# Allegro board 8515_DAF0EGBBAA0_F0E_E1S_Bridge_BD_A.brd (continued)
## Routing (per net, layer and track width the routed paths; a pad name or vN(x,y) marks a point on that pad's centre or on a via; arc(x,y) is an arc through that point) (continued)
FM_PRSNT_E1S_1_R_N: length 5.2
  TOP w0.109: U35.T14 131.82,31.43 131.58,31.2 v3(131.58,30.73) 131.58,30.25 R572.2 131.95,29.61 131.95,28.2 131.84,28.09 R556.1
FM_PRSNT_E1S_2_N: length 128.1
  TOP w0.109: v3(133.48,26.39) R557.2 ; v3(82.55,38) 83.03,38 83.14,37.9 J6.A12
  IN1 w0.124: v3(118.32,59.79) 118.54,59.79 119.28,60.53 120.68,60.53 121.48,61.33 123.41,61.33 124.19,60.55 128.22,60.55 128.71,61.05 131.27,61.05 131.87,60.45 132.66,60.45 133.33,61.13 135.43,61.13 136.21,60.34 136.21,54.17 136.08,54.04 136.08,52.7 136.21,52.57 136.21,49.61 136.13,49.54 136.13,46.32 135.94,46.13 135.94,44.1 136.6,43.45 136.6,39.75 137.19,39.15 138.66,39.15 139.15,38.67 142.37,38.67 143.13,37.91 143.13,36.79 143,36.67 143,31.92 141.63,30.55 141.63,29.07 142.16,28.54 142.16,26.27 140.41,24.52 138.93,24.52 138.15,25.3 136.47,25.3 135.92,25.85 134.01,25.85 v3(133.48,26.39)
  IN2 w0.124: v3(82.55,38) 83.31,37.24 86.49,37.24 92.33,43.08 93.75,43.08 95.66,41.17 100.45,41.17 100.72,40.9 107.51,40.9 107.98,40.43 v3(107.98,39.74)
  BOTTOM w0.109: v3(118.32,59.79) 118.32,59.76 118.16,59.6 118.16,56.16 117.74,55.13 116.99,54.39 116.51,54.07 116.22,53.95 114.22,51.94 114.22,50.19 111.59,47.57 110.59,47.57 108.78,45.76 108.78,41.04 v1(108.37,40.63) 108.23,40.49 108.23,40.21 107.98,39.96 v3(107.98,39.74)
FM_PRSNT_E1S_2_R_N: length 5.8
  TOP w0.109: R557.1 133.55,28.09 133.99,28.52 133.99,29.61 R573.2 133.88,30.53 133.88,31.09 133.03,31.95 v4(132.62,31.95) U35.T15
FM_PRSNT_E1S_3_N: length 56.2
  TOP w0.109: v3(106.76,37.31) 107.35,37.9 J7.A12 ; R694.2 v3(132.46,26.39)
  IN2 w0.124: v3(106.76,37.31) 106.76,36.86 106.89,36.74 108.35,36.74 110.04,38.42 110.04,39.27 110.4,39.63 111.06,39.63 111.33,39.36 114.18,39.36 115.79,40.97 115.79,43.75 116.35,44.31 118.18,44.31 118.8,43.69 119.69,43.69 120.1,43.29 120.1,41.6 119.6,41.11 119.09,41.11 118.85,40.87 118.85,36.12 119.05,35.92 120.6,35.92 120.95,35.57 120.95,34.6 121.44,34.11 122.76,34.11 122.95,33.92 122.95,33.88 122.98,33.85 122.98,33.55 122.95,33.52 122.95,33.08 122.98,33.05 122.98,32.75 122.95,32.72 122.95,30.32 123.62,29.65 125.52,29.65 126.01,30.14 132.24,30.14 132.86,30.77 v3(132.86,30.88)
  BOTTOM w0.109: v3(132.86,30.88) 132.86,29.54 v1(132.77,29.45) 132.77,29.05 132.92,28.89 132.92,28.3 132.46,27.84 v3(132.46,26.39)
FM_PRSNT_E1S_3_R_N: length 7.3
  TOP w0.109: R694.1 132.84,28.09 132.97,28.21 132.97,29.61 R697.2 132.72,30.37 133.02,30.37 133.32,30.67 133.32,31.15 133.1,31.37 132.57,31.37 132.21,31.73 132.21,32.91 U35.R14
FM_PWRDIS_E1S_0: length 121.2
  TOP w0.109: R542.2 v3(123.32,26.67) ; J4.B12 v3(29.34,37.89)
  IN2 w0.124: v3(29.34,37.89) 29.31,37.89 28.87,38.33 28.87,39.26 29.18,39.57 30.71,39.57 31.19,39.09 32.64,39.09 33.86,40.31 37.08,40.31 38.53,41.76 39.85,41.76 41.16,40.45 41.16,39.14 41.28,39.01 48.9,39.01 49.1,39.22 50.85,39.22 52.04,38.02 52.04,36.86 50.44,35.26 50.44,28.17 57.26,21.36 85.06,21.36 87.87,24.17 95.32,24.17 98.13,21.36 109.6,21.36 111.73,23.5 112.65,23.5 113.62,24.47 116.52,24.47 116.79,24.73 121.38,24.73 v3(123.32,26.67)
FM_PWRDIS_E1S_1: length 101.3
  TOP w0.109: J5.B12 52.12,37.9 v3(51.56,37.34) ; R544.2 v3(126.36,26.67)
  IN2 w0.124: v3(51.56,37.34) 51.56,37.02 49.97,35.43 49.97,28.11 57.1,20.98 82.28,20.98 88.85,14.41 95.28,14.41 101.85,20.99 109.76,20.99 110.12,21.34 112.4,21.34 113.11,22.05 113.11,23.32 113.74,23.95 116.71,23.95 117.29,23.37 120.58,23.37 122.38,25.17 124.87,25.17 v3(126.36,26.67)
FM_PWRDIS_E1S_2: length 91
  TOP w0.109: J6.B12 80.06,37.9 80.26,38.1 80.26,38.83 80.65,39.21 80.65,42.75 84.17,46.28 84.68,46.28 v3(86.16,47.75) ; v3(95.3,23.14) 94.24,23.14 93.61,23.77 89.08,23.77 88.8,24.05 88.8,25.86 87.66,27 87.66,27.95 87.03,28.58 87.03,29 v3(86.7,29.34) ; R545.2 v3(125.35,26.67)
  IN1 w0.124: v3(95.3,23.14) 100.56,23.14 104.32,19.39 108.81,19.39 110.21,17.99 113.08,17.99 113.28,17.78 114.94,17.78 116.72,19.57 116.72,19.98 118.71,21.97 121.79,21.97 122.54,22.72 122.54,23.24 125.35,26.05 v3(125.35,26.67)
  IN2 w0.124: v3(92.35,42.42) 88.96,39.02 88.96,37.22 88.49,36.75 87.71,36.75 86.79,35.84 86.79,30.76 86.41,30.38 86.41,29.68 86.7,29.4 v3(86.7,29.34)
  BOTTOM w0.109: v3(92.35,42.42) 92.35,45.77 91.44,46.69 86.49,46.69 86.16,47.02 v3(86.16,47.75)
FM_PWRDIS_E1S_3: length 28.6
  TOP w0.109: J7.B12 105.55,37.9 105.68,38.02 105.68,39.01 106.05,39.37 106.05,42.75 v3(107.44,44.14) 108.26,44.96 110.1,44.96 110.24,44.82 110.24,39.89 110.37,39.75 112.78,39.75 113.2,39.33 113.2,35.88 113.48,35.59 114.26,34.82 114.46,34.62 117.14,34.62 117.58,35.05 R700.2
FM_PWRDIS_E1S_R_0: length 6.9
  TOP w0.109: U35.T7 125.6,31.89 125.6,31.72 124.72,30.85 123.67,30.85 123.48,30.72 123.32,30.47 R565.2 123.83,29.61 123.83,28.2 123.72,28.09 R542.1
FM_PWRDIS_E1S_R_1: length 6.6
  TOP w0.109: U35.R8 127.38,32.93 127.38,31.98 126.94,31.54 126.94,30.47 126.59,30.12 R566.2 126.36,30.07 126.87,29.57 126.87,28.21 126.75,28.09 R544.1
FM_PWRDIS_E1S_R_2: length 5.7
  TOP w0.109: R545.1 125.62,28.09 125.86,28.32 125.86,29.61 R568.2 125.35,30.4 v3(126.49,31.54) 127.02,32.07 U35.T8
FM_PWRDIS_E1S_R_3: length 4.6
  TOP w0.109: R701.2 R700.1 119.27,35.29 120.52,36.55 120.52,37.19 120.63,37.3 U35.K1
HSC_SEL_ID0: length 10.4
  TOP w0.109: U35.F11 v4(129.82,40.9)
  BOTTOM w0.109: v4(129.82,40.9) 129.41,41.3 129.41,44.41 129.68,44.68 v1(129.68,45.37) 129.9,45.37 130.35,45.83 130.56,46.32 R519.1 131.06,47.48 131.06,48.58 130.56,49.09 R518.2
HSC_SEL_ID1: length 8.2
  TOP w0.109: R527.2 137.16,49.13 137.16,47.69 137.01,47.33 R528.1 136.65,46.52 v3(136.8,46.37) 136.16,46.37 133.49,43.7 U35.B16
HSC_SEL_ID2: length 14.5
  TOP w0.109: U35.C15 133.02,43.31 133.86,43.31 136.44,45.89 137.01,45.89 137.19,46.07 137.89,47.75 137.89,50.83 137.16,51.56 v3(136.73,51.56) 136.32,51.56 135.89,51.99 R533.1 R532.2
INA230_E1S_0_A0: length 4.8
  TOP w0.109: U11.2 12.83,50.8 12.32,51.31 12.32,51.58 R221.1 R219.1 9.63,52.22 9.4,52.45 v2(9.27,52.45)
INA230_E1S_0_A1: length 5.8
  TOP w0.109: U11.1 13.26,51.62 R223.1 R218.1 9.54,53.19 v2(8.76,53.98)
INA230_E1S_0_ALERT_R_N: length 3.9
  TOP w0.109: U11.3 12.05,50.3 R222.1 R217.1 9.63,50.06 v2(9.53,50.16)
INA230_E1S_1_A0: length 4.8
  TOP w0.109: U12.2 38.97,49.04 38.67,49.34 38.67,49.48 38.11,50.05 38.1,50.05 R237.1 ; R237.1 37.47,50.06 R234.1 ; R237.1 38.1,51.31 v2(37.72,51.69)
INA230_E1S_1_A1: length 6.3
  TOP w0.109: R233.1 v3(41.97,51.69) 41.27,51.69 41.21,51.63 v2(41.2,51.63) 40.53,52.3 39.6,52.3 39.22,51.92 R236.1 39.39,51.52 U12.1
INA230_E1S_1_ALERT_R_N: length 5
  TOP w0.109: R232.1 36.07,46.48 v2(36.07,47.62) 36.34,47.9 R238.1 38.25,47.9 38.86,48.51 38.86,48.54 U12.3
INA230_E1S_2_A0: length 4.6
  TOP w0.109: R249.1 62.19,33.17 R253.1 62.97,31.77 63.5,31.24 v2(63.5,31.11) 64.16,31.77 U13.2
INA230_E1S_2_A1: length 4.9
  TOP w0.109: v2(65.02,35.05) 64.62,34.65 R248.1 63.63,33.8 R252.1 64.39,33.66 65.05,33 U13.1
INA230_E1S_2_ALERT_R_N: length 5.1
  TOP w0.109: U13.3 64.52,31.27 64.52,31.24 64.39,31.11 64.39,30.25 R251.1 R247.1 61.72,30.88 v2(61.72,30.99)
INA230_E1S_3_A0: length 6.1
  TOP w0.109: U14.2 92.18,39.9 91.44,40.64 v2(91.44,42.16) 91.44,43.54 R267.1 R264.1
INA230_E1S_3_A1: length 5.5
  TOP w0.109: U14.1 92.73,41.93 93.47,42.67 v2(93.47,42.93) 93.47,43.18 93.07,43.58 R266.1 R263.1
INA230_E1S_3_ALERT_R_N: length 4.8
  TOP w0.109: R262.1 R268.1 90.93,38.25 v2(90.93,39.5) 91.06,39.5 91.16,39.4 U14.3
IO_EXP_INT: length 9.7
  TOP w0.109: U48.1 138.44,27.61 139.08,26.97 v3(139.92,26.97)
  BOTTOM w0.109: v3(139.92,26.97) 140.14,26.75 140.14,25.37 140.37,25.14 140.77,25.14 141,25.38 U44.7 141,26.88 141.45,27.33 141.73,27.33 142.29,27.89 R4604.1
IO_EXP_IO3: length 2
  TOP w0.109: v3(137.74,24.05) 137.4,23.71 U48.7
  BOTTOM w0.109: R4659.2 138.13,24.36 137.83,24.05 v3(137.74,24.05)
IO_EXP_IO4: length 1.9
  TOP w0.109: U48.8 137.41,23.06 v3(137.72,23.37)
  BOTTOM w0.109: v3(137.72,23.37) 137.79,23.44 R4660.2
IO_EXP_IO5: length 1.8
  TOP w0.109: U48.9 v3(137.69,22.41)
  BOTTOM w0.109: R4600.2 138.19,22.41 v3(137.69,22.41)
IO_EXP_IO6: length 1.8
  TOP w0.109: v3(137.72,21.71) 136.63,21.71 U48.10
  BOTTOM w0.109: v3(137.72,21.71) 138.22,21.71 R4601.2
IO_EXP_IO7: length 1.9
  TOP w0.109: U48.11 137.63,21.11 137.7,21.03 v3(137.7,21.05)
  BOTTOM w0.109: v3(137.7,21.05) 137.7,21.03 137.98,21.03 R4661.2
IO_EXP_IO8: length 2.7
  TOP w0.109: v3(143.74,19.81) 143.74,19.82 143.1,20.46 U48.13
  BOTTOM w0.109: R4662.2 143.74,19.86 v3(143.74,19.81)
IO_EXP_IO9: length 2.5
  TOP w0.109: v3(143.88,20.95) 143.73,20.95 143.57,21.11 U48.14
  BOTTOM w0.109: v3(143.88,20.95) 144.64,20.95 R4663.2
IO_EXP_IO10: length 2.4
  TOP w0.109: U48.15 143.54,21.76 v3(143.59,21.71)
  BOTTOM w0.109: R4664.2 143.6,21.69 v3(143.59,21.71)
IO_EXP_IO11: length 2.5
  TOP w0.109: U48.16 v3(143.89,22.41)
  BOTTOM w0.109: R4665.2 144.4,22.61 144.2,22.41 v3(143.89,22.41)
IO_EXP_IO12: length 2.6
  TOP w0.109: U48.17 v3(143.89,23.06)
  BOTTOM w0.109: v3(143.89,23.06) 144.14,23.06 144.6,23.52 R4666.2
IO_EXP_IO13: length 2.7
  TOP w0.109: U48.18 v3(143.89,23.71)
  BOTTOM w0.109: v3(143.89,23.71) 144.03,23.71 144.79,24.46 R4667.2
IO_EXP_IO14: length 3.3
  TOP w0.109: U48.19 v3(143.89,24.36)
  BOTTOM w0.109: v3(143.89,24.36) 143.96,24.36 144.81,25.2 R4668.2
IO_EXP_IO15: length 4.9
  TOP w0.109: U48.20 v3(143.84,25.01)
  BOTTOM w0.109: R4669.2 144.76,26.98 v1(144.8,26.94) 144.35,26.49 144.35,25.51 143.85,25.01 v3(143.84,25.01)
IO_EXP_RST: length 2.9
  BOTTOM w0.109: R4605.1 140.47,27.89 v1(140.35,27.77) 140.5,27.62 U44.6
IO_EXP_U44_IO4: length 7.3
  BOTTOM w0.109: R4597.1 136.24,19.91 v1(136.96,20.63) 136.96,20.1 137.32,19.74 139,19.74 140.46,20.34 141,20.89 U44.4
IRQ_INA230_E1S_0_ALERT_N: length 194.3
  TOP w0.109: v3(12.05,47.86) 12.05,49.02 R222.2 ; R620.1 v3(137.59,39.62)
  IN1 w0.124: v3(137.59,39.62) 137.59,40.18 137.85,40.44 137.85,50.83 138.53,52.47 138.53,55.61 138.08,56.07 138.08,58.3 138.69,58.91 v3(138.69,59.82)
  IN2 w0.124: v3(12.05,47.86) 15.18,47.86 16.18,46.86 20.57,46.86 22.91,44.53 29.41,44.53 30.94,46.05 31.93,46.05 33.34,47.46 36,47.46 38.53,49.99 42.16,49.99 43.23,48.92 43.23,47.57 43.95,46.85 45.86,46.85 49.39,43.32 55.36,43.32 57.58,45.54 58.53,45.54 63.78,50.8 63.78,52.48 64.72,53.42 64.72,58.67 65.94,59.9 70.29,59.9 71.08,59.11 71.08,57.2 70.8,56.92 70.6,56.92 70.32,56.65 70.32,56.21 70.6,55.94 72.1,55.94 72.98,55.06 72.98,46.05 74.88,44.15 81.49,44.15 83.14,45.8 98.17,45.8 99.94,44.02 106.48,44.02 107.64,45.18 108.3,45.18 110.24,47.12 110.48,47.12 111.46,48.11 112.75,48.64 114.78,50.68 114.78,51.04 114.78,51.89 118.49,55.6 118.49,56.67 118.77,56.95 122.81,56.95 123.26,57.39 123.26,59.32 123.95,60.02 125.85,60.02 125.93,60.1 127.69,60.1 128.78,61.19 131.26,61.19 132.63,59.82 v3(138.69,59.82)
IRQ_INA230_E1S_0_ALERT_R_N: length 4.9
  TOP w0.109: R620.2 135.74,39.74 135.23,40.26 v3(135.23,41.05) 135.23,41.36 134.89,41.71 133.02,41.71 U35.E15
IRQ_INA230_E1S_1_ALERT_N: length 152.3
  TOP w0.109: R238.2 37.39,46.89 v5(37.39,45.92)
  IN2 w0.124: v3(131.18,51.77) 131,51.6 131,50.68 132.07,49.6 132.07,46.4 131.85,46.17 131.85,38.89 132.62,38.11 132.62,32.62 133.55,31.69 133.55,30.56 132.71,29.72 126.29,29.72 125.85,29.28 125.85,28.49 125.46,28.1 113.42,28.1 113.3,27.99 112.77,27.99 110.98,26.19 110.98,25.61 109.35,23.98 97.61,23.98 95.43,26.16 90.39,26.16 90.06,26.49 87.99,26.49 84.19,22.7 69.68,22.7 68.08,24.3 68.08,25.73 68.04,25.77 67.65,25.77 67.08,26.34 66.94,26.34 65.93,27.34 65.64,27.34 65.37,27.62 65.37,27.82 64.83,28.35 64.04,28.35 63.63,28.76 62.81,28.76 62.4,28.35 61.8,28.35 61.1,29.05 61.1,30.01 60.35,30.76 58.34,30.76 57.93,31.17 57.93,31.92 57.49,32.36 55.14,32.36 54.07,33.43 54.07,39.63 52.9,40.79 49.99,40.79 48.63,42.15 43.32,42.15 40.56,44.91 38.4,44.91 v5(37.39,45.92)
  BOTTOM w0.109: R621.1 136.65,50.63 137.32,51.3 137.32,51.94 136.16,53.1 136.16,53.37 135.52,54.02 135.09,54.02 134.63,53.57 133.3,53.57 132.51,52.79 132.51,51.89 132.14,51.52 131.43,51.52 v3(131.18,51.77)
IRQ_INA230_E1S_1_ALERT_R_N: length 13.7
  TOP w0.109: U35.E14 v4(132.22,41.7)
  BOTTOM w0.109: R621.2 137.29,49.64 137.4,49.53 137.4,44.63 136.76,43.99 v1(136.76,42.2) 136.26,41.7 v4(132.22,41.7)
IRQ_INA230_E1S_2_ALERT_N: length 111.9
  TOP w0.109: R251.2 64.03,28.78 64.03,27.97 64.14,27.86 v3(64.65,27.86)
  IN2 w0.124: v3(134.23,49.08) 133.36,49.08 133.11,48.82 133.11,45.6 132.6,45.09 132.6,38.92 133.42,38.1 133.42,32.45 134.03,31.83 134.03,30.43 132.85,29.25 127.15,29.25 126.91,29 126.91,28.33 126.23,27.66 113.58,27.66 113.48,27.56 112.95,27.56 111.4,26.01 111.4,25.27 109.68,23.55 97.24,23.55 95.76,25.03 87.23,25.03 84.46,22.26 61.62,22.26 59.46,24.41 59.46,25.76 61.17,27.47 63.03,27.47 63.23,27.67 64.46,27.67 v3(64.65,27.86)
  BOTTOM w0.109: v3(134.23,49.08) 134.62,48.69 R622.1
IRQ_INA230_E1S_2_ALERT_R_N: length 8.4
  TOP w0.109: U35.E13 v4(131.42,41.7)
  BOTTOM w0.109: R622.2 134.62,44.16 v1(134.6,44.14) 134.6,43.42 134.49,43.31 132.8,43.31 132.42,42.92 131.98,42.92 131.83,42.77 131.83,42.27 131.42,41.85 v4(131.42,41.7)
IRQ_INA230_E1S_3_ALERT_N: length 98.2
  TOP w0.109: R268.2 92.02,36.94 92.05,36.91 v3(92.1,36.91) ; v3(135.25,60.31) 135.25,60.84 135.47,61.05 139.36,61.05 140.38,60.03 140.38,54.25 138.68,52.54 138.68,47.6 137.58,44.97 137.58,42.65 138.83,39.64 R726.1
  IN1 w0.124: v3(117.08,44.79) 119.25,46.96 119.25,54.65 119.71,55.76 119.98,56.03 120.44,56.22 123.37,56.22 123.5,56.1 123.5,55.09 123.87,54.72 127.14,54.72 127.94,53.92 128.76,53.92 130.78,55.94 132.01,55.94 133.22,56.44 135.25,58.47 v3(135.25,60.31)
  IN2 w0.124: v3(92.1,36.91) 92.1,35.44 92.44,35.11 95.96,35.11 96.45,35.6 100.88,35.6 101.74,36.46 101.74,37.27 102.51,38.04 104.12,38.04 106.49,40.41 107.24,40.41 107.51,40.14 107.51,39.54 107.78,39.26 108.22,39.26 110.24,41.29 110.24,43.43 111.95,45.14 111.95,46.15 112.27,46.47 112.66,46.73 113.81,46.73 114,46.54 115.52,46.54 117.08,44.98 v3(117.08,44.79)
IRQ_INA230_E1S_3_ALERT_R_N: length 8.4
  TOP w0.109: U35.F15 133.01,40.89 134.17,40.89 134.59,40.47 134.59,39.75 135.22,38.23 135.36,38.09 137.82,38.09 v3(138.03,37.88) R726.2
IRQ_P3V3_E1S_0_FLT_N: length 133
  TOP w0.109: U35.P2 v4(121.82,33.7) ; U26.C7 14.5,42.36 v3(14.86,42.72) ; v3(16.62,44.78) R191.1 16.27,44.41 16.15,44.7 16.15,44.81 15.79,45.17 U7.6
  IN2 w0.124: v3(14.86,42.72) 14.58,43 14.58,44.04 15.32,44.78 v3(16.62,44.78) 16.62,44.34 17.14,43.81 22.55,43.81 22.68,43.94 29.43,43.94 31.12,45.62 32.11,45.62 33.51,47.03 38.87,47.03 39.52,46.38 45.73,46.38 49.21,42.9 52.62,42.9 55.36,40.16 55.36,39.22 61.04,33.54 61.04,33.37 61.04,33.2 62,32.23 62,31.21 62.16,31.05 62.16,31.05 62.69,30.52 63.97,30.52 65.43,29.05 66.8,29.05 69.43,26.42 75.5,26.42 78.29,23.62 83.9,23.62 87.63,27.35 90.41,27.35 90.7,27.06 94.96,27.06 95.89,27.99 100.39,27.99 101,27.38 104.8,27.38 105.84,28.42 108.81,28.42 109.44,27.79 111.21,27.79 112.26,28.84 112.87,28.84 113.95,29.93 117.27,29.93 117.37,30.03 120.85,30.03 121.12,30.29 121.12,32.34 121.48,32.7 121.48,33.36 v4(121.82,33.7)
IRQ_P3V3_E1S_1_FLT_N: length 103.6
  TOP w0.109: U27.C7 43.58,41.51 v3(43.54,41.55) ; v3(44.89,43.17) 44.82,43.11 U8.6 ; U35.P3 v4(122.62,33.7)
  IN2 w0.124: v3(44.89,43.17) 45.42,42.65 48.74,42.65 50.16,41.22 53.24,41.22 54.81,39.65 v3(54.81,35.97) 54.81,33.68 55.68,32.82 57.91,32.82 58.37,32.36 58.37,31.6 58.63,31.34 61.15,31.34 62.59,29.89 63.12,29.89 64.19,28.82 64.98,28.82 65.28,28.52 66.65,28.52 68.51,26.65 68.51,24.48 69.86,23.13 84.01,23.13 87.81,26.92 90.23,26.92 90.57,26.59 104.62,26.59 106.02,27.99 108.46,27.99 109.12,27.33 111.51,27.33 112.59,28.41 113.1,28.41 114.18,29.5 117.5,29.5 117.59,29.59 121.16,29.59 121.56,30 121.56,32.08 122.2,32.72 122.2,33.28 v4(122.62,33.7)
  BOTTOM w0.109: v3(43.54,41.55) 43.54,41.89 43.76,42.11 R193.1 44.27,42.14 44.37,42.24 44.37,42.66 v3(44.89,43.17)
IRQ_P3V3_E1S_2_FLT_N: length 74.9
  TOP w0.109: R202.1 67.9,26.19 v3(67.84,26.24) U10.6 ; v3(112.1,25.22) 112.1,26.27 114.24,28.41 114.24,30.74 115.51,32.01 115.8,32.01 116.04,31.77 116.04,31.68 116.16,31.57 117.08,31.57 117.31,31.34 117.61,31.14 117.67,31.11 118.59,31.11 120.11,31.75 121.02,32.65 v4(121.02,32.9) U35.R1 ; v3(66.32,23.8) 65.96,23.44 U28.C7
  IN1 w0.124: v3(67.84,26.24) 67.84,25.67 66.32,24.15 v3(66.32,23.8) 66.73,23.39 70.94,23.39 72.82,25.27 76.81,25.27 80.17,28.63 82.31,28.63 83.6,27.34 83.69,27.34 84.6,26.43 84.95,26.43 90.34,31.83 94.49,31.83 95.4,30.91 101.73,30.91 104.12,28.53 108.79,28.53 v3(112.1,25.22)
IRQ_P3V3_E1S_3_FLT_N: length 42.1
  TOP w0.109: U35.R2 121.77,32.86 121.77,32.39 121.64,32.07 120.76,31.18 119.6,30.7 118.08,29.69 117.35,28.95 v4(117.35,28.65) ; R200.1 95.46,32.66 v3(94.97,32.66) 94.95,32.64 U9.6 ; v3(93.32,29.95) 92.96,29.59 U29.C7
  IN1 w0.124: v3(94.97,32.66) 95.15,32.49 103.05,32.49 104.27,33.71 105.56,33.71 106.55,32.72 107.44,32.72 107.75,33.02 107.75,34 107.91,34.16 108.47,34.16 108.82,33.81 109.75,33.81 110.11,34.17 110.11,34.74 110.23,34.87 112.22,34.87 114.71,32.38 114.71,31.11 115.93,29.9 117.07,29.9 117.35,29.62 v4(117.35,28.65)
  IN2 w0.124: v3(94.97,32.66) 94.97,31.6 v3(93.32,29.95)
IRQ_P3V3_EDGE_FLT_N: length 31.6
  TOP w0.109: R309.2 122.1,21.63 122.24,21.49 122.24,20.52 v3(121.81,20.08) ; U35.P10 v4(129.01,33.7)
  BOTTOM w0.109: v4(129.01,33.7) 129.44,34.12 130,34.12 130.2,33.92 130.2,33.54 130.6,33.14 130.6,32.66 131.94,31.33 133.06,31.33 133.4,30.99 133.46,30.84 133.46,30.66 133.37,30.45 133.37,29.59 133.94,29.03 133.94,28.51 132.97,27.54 132.97,26.21 132.19,25.43 132.19,23.31 131.93,23.04 131.93,20.98 130.44,19.49 129.75,19.49 129.37,19.11 126.36,19.11 125.94,19.53 122.02,19.53 121.81,19.75 v3(121.81,20.08)
IRQ_P12V_E1S_0_FLT_N: length 137.8
  TOP w0.109: U22.C7 19.97,57.45 v3(20.35,57.45) ; v3(23.24,56.39) 23.04,56.59 U3.6 ; U35.N4 v4(123.42,34.5)
  IN1 w0.124: v4(123.42,34.5) 123.26,34.5 122.89,34.87 122.43,34.87 122.22,35.08 122.22,35.59 122.1,35.71 119.99,35.71 119.84,35.56 116.15,35.56 115.97,35.75 114.34,35.75 113.27,36.82 111.81,36.82 111.31,37.32 110.59,37.32 109.31,38.6 109.31,38.96 109.31,39.21 108.26,40.26 105.67,40.26 103.3,42.62 97.14,42.62 96.45,43.31 94.99,43.31 92.35,45.95 85.84,45.95 84.19,44.29 83.83,44.29 83.41,44.29 82.93,44.77 82.52,44.77 81.19,43.44 79.1,43.44 77.67,42.01 74.7,42.01 72.77,40.08 72.77,38.05 70.46,35.74 67.26,35.74 62.94,40.06 60.96,40.06 58.3,42.72 56.9,42.72 55.98,43.64 48.62,43.64 45.9,46.35 41.04,46.35 40.16,47.24 32.64,47.24 30.1,44.7 23.88,44.7 22.27,46.31 22.27,53.11 22.36,53.2 22.36,55.51 v3(23.24,56.39)
  IN2 w0.124: v3(20.35,57.45) 22.17,57.45 v3(23.24,56.39)
  BOTTOM w0.109: R171.1 23.24,58.43 v3(23.24,56.39)
IRQ_P12V_E1S_1_FLT_N: length 114.8
  TOP w0.109: v3(45.03,56.59) 45.05,56.6 45.05,56.76 44.6,57.2 U23.C7 ; v3(90.3,39.01) 90.3,42.98 89.94,43.33 89.94,45.11 89.46,45.59 84.17,45.59 v3(83.79,45.21) ; v3(47.83,55.7) 47.83,55.88 47.81,55.9 U4.6 ; U35.P4 v4(123.42,33.7)
  IN1 w0.124: v3(105.99,35.69) 106.65,36.34 108.23,36.34 109.24,35.33 112.37,35.33 115.42,32.28 116.89,32.28 117.09,32.49 118.16,32.49 118.36,32.28 121.26,32.28 122.3,33.32 123.04,33.32 v4(123.42,33.7) ; v3(83.79,45.21) 83.22,45.78 82.31,45.78 80.83,44.3 74.3,44.3 72.34,46.25 72.34,48.51 70.61,50.24 67.49,50.24 63.04,45.8 57.18,45.8 55.96,44.58 48.9,44.58 47.75,45.72 47.75,55.45 47.83,55.52 v3(47.83,55.7) ; v3(96.94,33.31) 96.56,33.31 96.22,33.66 96.22,34.77 95.96,35.03 92.46,35.03 91.26,36.22 91.26,38.05 v3(90.3,39.01)
  IN2 w0.124: v3(45.03,56.59) 45.03,56.44 45.77,55.7 v3(47.83,55.7) ; v3(105.99,35.69) 105.85,35.55 105.47,35.55 104.37,34.44 101.22,34.44 99.39,32.61 97.64,32.61 v3(96.94,33.31)
  BOTTOM w0.109: R174.1 47.93,56.8 48.01,56.72 48.01,55.88 v3(47.83,55.7)
IRQ_P12V_E1S_2_FLT_N: length 78.3
  TOP w0.109: v3(70.83,56.42) 70.56,56.69 70.36,56.69 70.2,56.85 U24.C7 ; U5.6 73.33,54.18 v3(74.49,53.03) 74.41,52.95 R179.1 ; U35.P1 v4(121.04,33.72)
  IN1 w0.124: v3(110.64,39.14) 110.64,39.63 108.77,41.5 108.3,41.5 108.3,41.49 106.18,41.49 103.75,43.92 98.67,43.92 95.41,47.18 83.21,47.18 82.73,46.7 81.89,46.7 80.4,45.21 74.75,45.21 73.3,46.67 73.3,52.6 73.72,53.03 v3(74.49,53.03)
  IN2 w0.124: v3(70.83,56.42) 72.3,56.42 73.85,54.87 73.85,53.66 v3(74.49,53.03) ; v4(121.04,33.72) 120.06,34.7 118.75,34.7 118.5,34.94 117.58,34.94 117.03,34.39 113.87,34.39 112.57,35.69 109.56,35.69 109.43,35.81 109.43,36.63 110.64,37.84 v3(110.64,39.14)
IRQ_P12V_E1S_3_FLT_N: length 61.3
  TOP w0.109: R182.1 98.88,53.54 98.88,54.27 v3(99.15,54.54) 98.81,54.89 U6.6 ; U25.C7 95.68,57 96.17,56.52 v3(96.39,56.52) ; U35.P5 v4(124.22,33.7) ; v3(109.58,45.59) 109.65,45.61 110.45,45.28 113.17,45.28 113.83,45.01 114.32,44.68 115.39,43.61 115.39,42.13 114.93,41.02 113.58,39.67 113.58,36.04 113.76,35.87 114.42,35.2 114.83,35.2 114.84,35.2 v3(114.93,35.1)
  IN1 w0.124: v4(124.22,33.7) 123.96,33.7 123.55,34.11 122.28,34.11 121.89,34.49 119.86,34.49 119.35,35 117.75,35 117.2,34.44 115.59,34.44 v3(114.93,35.1) ; v3(99.15,54.54) 98.86,54.25 98.86,52.81 98.33,52.28 98.33,46.83 100.31,44.85 105.48,44.85 106.47,45.84 107.69,45.84 108.92,47.07 110.24,47.07 110.72,46.58 110.72,45.8 110.35,45.42 109.74,45.42 v3(109.58,45.59)
  IN2 w0.124: v3(96.39,56.52) 96.49,56.41 98.5,56.41 98.62,56.29 98.62,54.9 98.97,54.54 v3(99.15,54.54)
IRQ_P12V_EDGE_FLT_N: length 2.8
  TOP w0.109: U35.T11 v4(129.02,32.1)
  BOTTOM w0.109: R4589.2 128.9,30.63 128.9,31.99 v4(129.02,32.1)
IRQ_P12V_EDGE_FLT_N_R: length 169.2
  TOP w0.109: v3(7.67,29.47) 8.14,29.47 U33.C7 ; U34.9 18.48,33.96 18.59,34.07 18.59,34.62 v3(19.27,35.3)
  IN1 w0.124: v3(116.25,19.96) 114.51,18.21 113.46,18.21 113.25,18.42 110.39,18.42 108.99,19.82 104.49,19.82 99.94,24.37 96.61,24.37 96.38,24.6 89.61,24.6 85.7,20.7 74.85,20.7 71.76,17.6 62.06,17.6 61.45,18.21 60.65,18.21 59.72,19.14 53.46,19.14 53.44,19.13 53.44,19.13 48.84,14.53 42.6,14.53 38.17,18.95 v3(26.51,18.95)
  IN2 w0.124: v3(7.67,29.47) 8.15,29.47 8.33,29.65 8.33,31.18 8.86,31.71 8.86,35.14 8.66,35.35 8.66,36.15 8.93,36.42 8.98,36.42 10.27,37.72 11.76,37.72 15.7,36.09 18.95,36.09 19.27,35.76 v3(19.27,35.3) 19.9,35.3 23.5,31.7 23.5,19.94 24.48,18.95 v3(26.51,18.95)
  BOTTOM w0.109: v3(116.25,19.96) 117.36,19.96 117.45,20.05 117.54,20.05 120,22.51 120,22.72 121.01,23.74 124.48,23.74 125.1,23.12 125.1,22.24 125.42,21.92 129.56,21.92 129.86,22.22 129.86,22.51 129.7,22.88 129.7,25.41 129.96,25.67 129.96,26.72 129.89,26.78 129.89,28.87 129.6,29.16 129.57,29.16 R4589.1 129.69,29.59 129.9,29.59 R512.2
IRQ_P12V_HSC_ALERT1_N: length 8.2
  TOP w0.109: U35.R3 v4(122.62,32.9)
  BOTTOM w0.109: v4(122.62,32.9) 122.62,32.72 122.94,32.4 122.94,31.69 122.37,31.12 121.74,31.12 120.88,30.76 120.62,30.76 119.96,30.49 119.76,30.29 119.76,28.2 119.65,28.09 R707.2
IRQ_P12V_HSC_ALERT2_N: length 5.1
  TOP w0.109: v4(122.01,31.88) 122.14,32.02 122.14,32.41 122.22,32.48 U35.T2
  BOTTOM w0.109: R708.2 118.44,30.33 118.59,30.33 119.04,30.77 119.56,31.12 119.75,31.2 120.05,31.5 120.97,31.88 v4(122.01,31.88)
IRQ_SMB_ALERT_N: length 162.5
  TOP w0.109: v3(132.59,10.68) 132.59,10.29 130.02,7.72 115.63,7.72 115.05,8.3 113.44,8.97 108.18,8.97 106.37,10.77 v3(106.37,11.72)
  IN1 w0.124: v3(13.66,9.53) 13.77,9.64 14.41,9.64 14.53,9.52 21.05,9.52 24.68,13.15 24.68,16.72 25.1,17.13 27.4,17.13 27.9,17.64 34.61,17.64 40.25,12 55.36,12 56.18,11.18 97.65,11.18 98.44,11.96 106.14,11.96 106.37,11.73 v3(106.37,11.72) ; v3(132.59,10.68) 132.59,11.91 133.53,12.85 133.53,15.97 134.39,16.83 134.39,19.67 134,20.06 132.88,20.06 132.39,20.55 131.26,20.55 v3(129.39,22.42)
  BOTTOM w0.109: v3(129.39,22.42) 129.32,22.49 129.32,25.41 128.85,25.88 128.85,26.37 128.92,26.44 128.92,27.52 128.4,28.04 R185.2 128.8,28.09 128.91,28.2 128.91,29.08 128.67,29.32 R552.1 ; GF1.OCP_A11 v3(13.66,9.53)
IRQ_SMB_ALERT_R_N: length 6.2
  TOP w0.109: U35.P9 v4(128.22,33.7)
  BOTTOM w0.109: v4(128.22,33.7) 128.39,33.7 128.82,33.27 129.42,33.27 v1(129.69,33.01) 129.69,32.64 129.58,32.53 128.74,32.53 128.61,32.41 128.61,30.9 128.4,30.68 R552.2
IRQ_TMP75_ALERT_N: length 67.4
  TOP w0.109: U35.L4 v4(123.42,36.1)
  IN2 w0.124: v3(122.66,57.5) 120.84,57.5 119.79,58.55 117.78,58.55 117.5,58.27 117.5,56.01 113.85,52.35 113.85,50.96 112.26,49.37 111.48,49.05 104.62,49.05 103.84,48.26 103.84,45.9 103.25,45.31 100.57,45.31 97.14,48.74 v3(96.39,48.74) ; v3(127.05,56.49) 127.05,56.23 125.75,54.94 125.75,53.89 126.18,53.47 126.18,52.41 125.81,52.04 125.12,52.04 124.72,51.64 124.72,50.58 124.61,50.47 124.13,50.47 123.74,50.08 123.74,47.9 123.78,47.85 123.78,41.98 122.98,41.18 122.98,38.84 123.83,38 123.83,36.35 123.58,36.1 v4(123.42,36.1)
  BOTTOM w0.109: v3(122.66,57.5) 123.45,57.5 123.87,57.08 124.58,57.08 126.02,56.48 127.04,56.48 v3(127.05,56.49) ; R291.1 96.08,49.05 v3(96.39,48.74)
JTAG_BIC_DEBUG_R_TDO: length 3.5
  TOP w0.109: U35.A11 129.42,44.86 130.91,46.35 130.91,46.59 131.29,46.97 R674.2
JTAG_BIC_DEBUG_TCK: length 17.3
  TOP w0.109: R4585.2 v3(129.16,57.53) ; U35.D10 v4(129.01,42.5)
  BOTTOM w0.109: v3(129.16,57.53) 129.59,57.1 129.59,56.33 129.38,56.12 129.38,49.99 128.78,49.39 128.78,48.75 129.03,48.5 129.03,46.73 129.19,46.57 129.19,46.09 128.81,45.71 128.81,45.31 128.85,45.27 128.85,43.66 128.61,43.41 128.61,42.91 v4(129.01,42.5)
JTAG_BIC_DEBUG_TCK2: length 4.3
  TOP w0.109: U35.A13 131.02,44.73 131.23,44.95 131.23,44.96 v4(131.24,44.96)
  BOTTOM w0.109: R4615.2 133.6,46.09 v1(132.41,44.89) 131.3,44.89 v4(131.24,44.96)
JTAG_BIC_DEBUG_TCK_R: length 4.4
  TOP w0.109: 133.54,56.52 133.49,56.47 v3(131.86,56.47) 131.64,56.47 R4585.1 R4581.1
JTAG_BIC_DEBUG_TDI: length 18.7
  TOP w0.109: R4586.2 129.28,59.56 v3(129.13,59.41) ; U35.C10 v4(129.01,43.3)
  BOTTOM w0.109: v4(129.01,43.3) 129.15,43.43 129.15,45.4 129.25,45.65 129.52,45.92 129.88,45.92 130.11,46.15 130.16,46.27 130.16,46.49 130.04,46.62 130.04,48.74 129.74,49.46 129.74,55.88 129.97,56.11 129.97,58.76 129.31,59.41 v3(129.13,59.41)
JTAG_BIC_DEBUG_TDI2: length 5.7
  TOP w0.109: U35.D11 v4(129.82,42.5)
  IN1 w0.124: v4(129.82,42.5) 129.53,42.5 129.41,42.62 129.41,45.6 v3(128.74,46.27)
  BOTTOM w0.109: R4616.2 128.52,46.49 v3(128.74,46.27)
JTAG_BIC_DEBUG_TDI_R: length 4.4
  TOP w0.109: R4582.1 R4586.1 130.58,59.49 v3(131.21,58.86) 131.4,59.05 J2.8
JTAG_BIC_DEBUG_TDO: length 15.6
  TOP w0.109: J2.6 132.33,57.78 131.72,58.39 130.9,58.39 130.75,58.55 R4583.1 130.58,58.11 130.62,58.06 130.75,58.06 v3(131.22,57.59) ; R674.1 131.57,48.81 v3(131.35,49.02)
  BOTTOM w0.109: v3(131.22,57.59) 130.36,56.73 130.36,55.93 130.08,55.65 130.08,52.17 130.96,51.29 131.05,51.08 131.05,49.17 131.2,49.02 v3(131.35,49.02)
JTAG_BIC_DEBUG_TDO2: length 4.7
  TOP w0.109: U35.C11 v4(129.82,43.3)
  IN1 w0.124: v4(129.82,43.3) 129.82,43.35 130.19,43.72 130.19,45.78 129.68,46.28 v3(129.68,46.35)
  BOTTOM w0.109: v3(129.68,46.35) 129.68,46.83 R4617.2
JTAG_BIC_DEBUG_TMS: length 14.4
  TOP w0.109: v3(132.05,52.13) 132.05,52.12 131.95,52.01 131.95,50.71 131.37,50.13 131.37,49.68 132.08,48.98 132.08,46.38 131.45,45.75 130.79,45.75 129.82,44.77 v4(129.82,44.1) U35.B11 ; v3(131.12,54.02) 130,54.02 129.77,54.25 R4584.2
  BOTTOM w0.109: v3(132.05,52.13) 132.05,53.09 v3(131.12,54.02)
JTAG_BIC_DEBUG_TMS2: length 7.1
  TOP w0.109: U35.B12 v4(130.62,44.1)
  IN1 w0.124: v3(131.4,46.36) 131.36,46.32 130.74,46.32 130.62,46.19 v4(130.62,44.1)
  BOTTOM w0.109: v3(131.4,46.36) 131.54,46.5 v4(131.54,48.14) 131.54,48.56 131.92,48.94 131.92,49.29 R4618.2
JTAG_BIC_DEBUG_TMS_R: length 4.3
  TOP w0.109: R4584.1 R4580.1 130.94,55.5 v3(131.16,55.28) 131.38,55.5 132.11,55.5 132.36,55.24 J2.2
JTAG_BIC_NTRST1: length 7.2
  TOP w0.109: R675.2 132.46,49.17 133.1,48.53 133.1,47.24 132.82,46.97 R596.2 132.59,46.25 v4(132.27,45.94) 131.75,45.42 130.93,45.42 130.22,44.7 U35.A12
JTAG_BIC_NTRST2: length 10.4
  TOP w0.109: U35.B13 v4(131.42,43.3)
  BOTTOM w0.109: R4613.2 R4614.2 133.6,49.05 134.1,48.55 134.1,45.47 134.29,45.29 134.29,44.53 133.55,43.79 v1(133.29,43.79) 132.01,43.79 131.52,43.3 v4(131.42,43.3)
JTAG_BIC_SRST_N: length 3.7
  TOP w0.109: J2.10 132.56,60.33 132.16,60.73 v3(132.16,61.06) 131.62,61.59 R4587.1
LED_BIC_E1S_0: length 122
  TOP w0.109: v3(39.69,39.87) 37.28,39.87 37.21,39.8 35.64,39.8 35.19,39.36 R216.1 34.66,39.17 34.59,39.09 J4.A10 ; R551.2 v3(128.4,28.7)
  IN2 w0.124: v3(128.4,28.7) 128.24,28.7 126.96,27.42 126.96,26.53 125.06,24.63 122.4,24.63 120.11,22.34 118.52,22.34 117.97,22.89 115.37,22.89 114.96,22.48 114.96,21.01 113.47,19.52 112.06,19.52 111.5,20.08 102.16,20.08 95.63,13.55 87.68,13.55 87.08,14.15 62.19,14.15 49.11,27.23 49.11,36.2 47.21,38.1 40.43,38.1 39.69,38.84 v3(39.69,39.87)
LED_BIC_E1S_1: length 119.8
  TOP w0.109: R553.2 128.8,27.29 128.91,27.18 128.91,25.85 129.33,25.43 130.79,25.43 131.29,24.92 131.29,23.48 130.8,22.99 v3(130.16,22.99) ; v3(115.66,31.41) 114.65,30.39 114.65,26.54 112.83,24.72 112.83,21.21 113.12,20.92 114.69,20.92 v3(115.13,20.48) ; v3(62.51,34.47) 62.36,34.62 62.36,35.17 63.43,36.24 63.87,36.24 64.22,36.59 64.22,37.08 63.12,38.18 v2(63.12,39.42) 62.72,39.83 61.35,39.83 60.81,39.29 R231.1 60.74,39.17 60.67,39.1 J5.A10
  IN2 w0.124: v3(62.51,34.47) 62.87,34.47 64.25,33.09 64.25,31.99 65.94,30.29 67.35,30.29 67.67,30.6 69.14,30.6 69.37,30.37 69.37,28.75 70.44,27.68 79.5,27.68 80.26,28.45 83.19,28.45 83.81,27.83 85.53,27.83 86.94,28.41 88.04,29.51 91.67,29.51 91.81,29.37 93.53,29.37 95.61,31.45 95.61,33.12 96.72,34.24 98.58,34.24 99.29,34.95 103.91,34.95 104.6,35.64 104.83,35.64 105.52,36.33 108.14,36.33 109.83,34.65 109.83,31.75 110.17,31.41 v3(115.66,31.41)
  BOTTOM w0.109: v3(130.16,22.99) 130.16,22.77 130.24,22.58 130.24,22.06 129.69,21.51 124.31,21.51 122.47,23.35 121.38,23.35 119.9,21.88 119.9,20.83 119.4,20.32 118.36,20.32 117.37,19.33 116.03,19.33 115.13,20.23 v3(115.13,20.48)
LED_BIC_E1S_2: length 73.8
  TOP w0.109: R246.1 88.32,38.63 v2(87.83,39.12) 86.36,39.12 v3(86.11,38.86) 86.11,38.7 85.76,38.35 85.22,38.35 84.48,39.1 J6.A10 ; R554.2 v3(129.41,28.7)
  IN1 w0.124: v4(121.02,36.9) 121.42,36.5 126.07,36.5 126.19,36.38 126.19,33.91 127.58,32.51 128.07,32.51 128.52,32.07 128.52,31.26 129.41,30.37 v3(129.41,28.7)
  IN2 w0.124: v3(86.11,38.86) 87.5,38.86 92.13,43.48 93.98,43.48 95.91,41.56 100.82,41.56 100.98,41.4 109.35,41.4 109.81,41.86 109.81,43.74 111.52,45.45 111.52,46.35 112.19,47.02 113.02,47.36 113.78,47.36 114.15,47 117.82,47 118.3,46.52 118.69,46.52 120.41,46.52 122.22,44.7 122.22,38.11 v4(121.02,36.9)
LED_BIC_E1S_3: length 37.6
  TOP w0.109: v3(112.22,37.31) 111.8,37.74 R261.1 111.41,37.49 110.77,37.49 110.5,37.75 110.5,38.41 109.81,39.1 J7.A10 ; R725.2 v3(129.41,26.19)
  IN1 w0.124: v3(129.41,26.19) 129.42,26.19 130.95,27.73 130.95,30 130.28,30.68 130.28,32.31 129.26,33.32 127.62,33.32 126.98,33.96 126.98,38.07 126.65,38.41 123.41,38.41 122.93,38.89 117.41,38.89 117.02,39.28 116.36,39.28 115.77,39.88 114.75,39.88 113.7,38.83 112.73,38.83 112.22,38.33 v3(112.22,37.31)
LED_BIC_E1S_R_0: length 3.9
  TOP w0.109: R551.1 128.4,30.94 129.79,32.33 129.79,32.92 U35.R11
LED_BIC_E1S_R_1: length 5.4
  TOP w0.109: U35.T12 130.22,32.23 129.53,31.55 v3(129.53,31.25) 128.91,30.63 128.91,28.21 128.78,28.09 R553.1
LED_BIC_E1S_R_2: length 3.8
  TOP w0.109: U35.R12 130.61,32.91 130.61,32.21 130.07,31.68 130.07,31.16 129.41,30.49 R554.1
LED_BIC_E1S_R_3: length 5.4
  TOP w0.109: U35.T13 131.02,31.97 v3(130.76,31.71) 130.76,31.39 129.93,30.56 129.93,28.15 129.84,28.06 129.44,28.06 R725.1
LED_P12V_AUX: length 3.5
  TOP w0.109: v3(144.21,19.17) 144.75,18.63 v2(145.21,18.63) 145.21,19.27 144.91,19.57 D10.1
  BOTTOM w0.109: v3(144.21,19.17) 144.21,19.17 144.21,19.19 144.32,19.09 144.67,19.09 R296.2
LED_P12V_E1S_ALL_GOOD: length 10.4
  TOP w0.109: v3(145.68,26.41) 145.69,26.4 145.69,25.88 145.58,25.77 D11.C
  IN1 w0.124: v3(145.68,26.41) 144.95,26.41 144.83,26.54 144.83,29.03 144.42,29.44 144.42,31.63 144.71,31.92 v3(145.08,31.92)
  BOTTOM w0.109: v1(145.62,31.18) 145.62,31.38 v3(145.08,31.92) U17.D
LED_P12V_E1S_ALL_GOOD_R: length 11
  TOP w0.109: v3(145.66,27.05) 145.42,26.81 144.44,26.81 144.32,26.68 144.32,24.6 144.65,24.27 D11.A
  IN1 w0.124: v3(145.66,27.05) 145.66,30.33 145.53,30.45 v3(145.11,30.45)
  BOTTOM w0.109: R297.2 143.89,30 143.89,30.34 144.01,30.45 v1(144.38,30.45) v3(145.11,30.45)
LED_PWRGD_P12V_E1S_ALL: length 41.2
  TOP w0.109: U35.N5 v4(124.22,34.5)
  IN1 w0.124: v4(124.22,34.5) 124.4,34.5 124.79,34.11 125.25,34.11 125.43,33.93 125.43,32.57 125.76,32.24 126.51,32.24 126.94,31.81 126.94,30.83 127.15,30.62 127.79,30.62 128.94,29.47 128.94,25.77 129.29,25.42 131.69,25.42 131.92,25.64 131.92,26.56 132.74,27.38 133.76,27.38 134.24,26.9 136.47,26.9 137.26,26.11 138.65,26.11 v3(139.23,25.53) 140.28,25.53 141.35,26.6 141.35,28.2 140.82,28.73 140.82,30.35 140.01,31.17 140.01,32.68 v3(141.54,34.21)
  BOTTOM w0.109: v3(141.54,34.21) 140.91,34.21 140.8,34.32 140.8,35.88 140.92,36 v1(141.16,36) 141.4,36 141.54,35.87 R4670.1 ; R298.1 139.26,25.56 v3(139.23,25.53)
LED_PWRGD_P12V_E1S_ALL_R: length 4.3
  BOTTOM w0.109: U17.G C304.1 143.34,35.61 142.96,35.99 v1(142.52,35.99) 142.5,35.99 142.34,35.83 R4670.2
Net_78: length 0.6
  TOP w0.109: 131.82,42.9 v4(132.22,43.3)
Net_98: length 0.6
  TOP w0.109: 131.02,38.1 v4(131.42,37.7)
Net_99: length 0.6
  TOP w0.109: 132.62,37.3 v4(133.01,36.9)
Net_100: length 0.6
  TOP w0.109: 131.82,37.3 v4(132.22,36.9)
Net_101: length 0.6
  TOP w0.109: 130.22,42.9 v4(130.62,43.3)
Net_103: length 0.6
  TOP w0.109: 132.62,38.9 v4(133.01,39.3)
Net_104: length 0.6
  TOP w0.109: 129.42,41.3 v4(129.82,41.7)
Net_107: length 0.6
  TOP w0.109: 133.42,39.7 v4(133.82,40.1)
Net_110: length 0.6
  TOP w0.109: 132.62,39.7 v4(133.01,40.1)
Net_113: length 0.6
  TOP w0.109: 128.62,33.3 v4(129.01,32.9)
Net_117: length 0.6
  TOP w0.109: 130.22,35.7 v4(130.62,35.3)
Net_118: length 0.6
  TOP w0.109: 129.42,34.9 v4(129.82,34.5)
Net_119: length 0.6
  TOP w0.109: 131.82,38.1 v4(132.22,37.7)
Net_121: length 0.6
  TOP w0.109: 122.22,35.7 v4(121.82,35.3)
Net_122: length 0.6
  TOP w0.109: 130.22,34.9 v4(130.62,34.5)
Net_809: length 0.6
  TOP w0.109: 124.62,42.9 v4(124.22,43.3)
Net_811: length 0.6
  TOP w0.109: 123.82,42.9 v4(123.42,43.3)
OSC1_OE: length 4
  TOP w0.109: R319.1 121.16,53.01 v3(121.22,53.07) 121.24,53.09 121.54,53.09 121.67,53.21 121.67,55.15 121.78,55.26 OSC1.1
OSC1_VDD:
  vias: v3(123.7,53.72)
OSC1_VDD_R:
  vias: v3(124.07,55.74)
P3E_E1S_0_RX_DN0: length 43.7
  TOP w0.132: v3(30.54,35.1) 30.87,34.76 31.89,34.76 32.02,34.89 J4.A17
  BOTTOM w0.132: GF1.A17 29.45,3.16 29.58,3.29 29.58,5.19 29.78,5.6 30.29,6.64 32.69,10.07 32.83,10.86 v4(32.83,11.69) 32.83,14.23 25.23,23.46 25.23,23.47 25.06,23.67 24.03,29.03 24.02,29.61 24.24,30.16 25.83,34.07 26.87,34.79 27.47,34.79 27.47,34.8 30.23,34.8 v3(30.54,35.1)
P3E_E1S_0_RX_DN1: length 43.6
  TOP w0.132: J4.A20 33.6,33.09 33.73,32.96 34.33,32.96 v3(34.67,33.3)
  BOTTOM w0.132: GF1.A20 31.25,3.16 31.38,3.29 31.38,4.72 31.74,5.6 31.79,5.74 32.56,7.66 33.18,8.55 33.88,9.53 34.28,11.83 34.28,14.4 v4(29.81,19.83) 26.44,23.94 25.9,28.61 25.9,29.23 26.15,30.65 26.64,31.14 27.23,31.14 27.28,31.15 27.54,31.23 27.61,31.27 29.15,32.36 29.85,32.6 30.75,32.6 31.49,32.99 32.44,32.99 32.86,32.81 33.22,32.81 33.68,32.95 33.95,32.99 34.36,32.99 v3(34.67,33.3)
P3E_E1S_0_RX_DN2: length 36.7
  TOP w0.132: J4.A23 32.02,31.29 31.86,31.14 31.37,31.14 30.67,30.44 30.36,30.44 v3(30.03,30.78)
  BOTTOM w0.132: v3(30.03,30.78) 29.69,30.44 28.97,30.44 28.3,29.77 27.96,29.29 27.79,28.29 27.79,24.39 34.95,15.67 v4(35.08,15.51) 35.43,15.09 35.81,14.63 35.41,9.39 33.71,6.96 33.4,5.6 33.18,4.66 33.18,3.29 33.05,3.16 GF1.A23
P3E_E1S_0_RX_DN3: length 35.8
  TOP w0.132: v3(34.62,29.7) 34.28,29.36 33.73,29.36 33.6,29.49 J4.A26
  BOTTOM w0.132: v3(34.62,29.7) 34.28,29.36 33.4,29.36 32.77,28.72 32.77,27.77 33.16,27.2 35.25,24.24 35.4,24.03 35.45,23.96 35.65,23.65 35.83,23.39 35.85,23.29 v4(35.9,22.94) 35.96,22.54 36.14,21.27 36.52,20.99 37.11,21.08 37.26,20.97 37.33,20.47 37.22,20.32 36.63,20.23 36.35,19.86 36.46,19.08 36.83,18.8 37.43,18.89 37.57,18.77 37.65,18.28 37.54,18.13 36.94,18.04 36.66,17.66 37.18,14.08 37.01,12.07 36.99,11.95 36.69,8.49 35.46,7.26 34.98,6.19 34.98,3.29 34.85,3.16 GF1.A26
P3E_E1S_0_RX_DP0: length 43.7
  TOP w0.132: v3(30.54,34.09) 30.87,34.42 31.89,34.42 32.02,34.29 J4.A18
  BOTTOM w0.132: v3(30.54,34.09) 30.16,34.46 27.61,34.46 27.61,34.45 26.98,34.45 26.11,33.85 25.96,33.48 26.07,33.21 25.93,32.85 25.66,32.74 25.51,32.37 25.62,32.1 25.47,31.74 25.21,31.62 25.06,31.26 25.17,30.99 25.02,30.63 24.75,30.51 24.36,29.55 24.37,29.06 24.37,29.06 25.37,23.82 25.49,23.68 v4(27.38,21.38) 33.17,14.35 33.17,10.83 33.01,9.94 30.58,6.47 30.16,5.6 29.92,5.11 29.92,3.29 30.05,3.16 GF1.A18
P3E_E1S_0_RX_DP1: length 43.6
  TOP w0.132: J4.A21 33.6,32.49 33.73,32.62 34.33,32.62 v3(34.67,32.29)
  BOTTOM w0.132: GF1.A21 31.85,3.16 31.72,3.29 31.72,4.66 32.1,5.6 32.11,5.61 32.87,7.5 33.46,8.35 33.46,8.35 34.2,9.4 34.63,11.8 34.63,14.52 32.67,16.9 v4(32.3,17.35) 26.76,24.08 26.66,24.97 26.84,25.2 26.8,25.59 26.57,25.77 26.52,26.22 26.7,26.44 26.66,26.83 26.43,27.02 26.38,27.41 26.56,27.63 26.52,28.03 26.29,28.21 26.24,28.63 26.24,29.2 26.47,30.49 26.78,30.8 27.25,30.8 27.36,30.81 27.68,30.92 27.8,30.99 29.31,32.05 29.91,32.26 30.83,32.26 31.57,32.65 32.37,32.65 32.79,32.47 33.28,32.47 33.76,32.62 33.97,32.65 34.3,32.65 v3(34.67,32.29)
P3E_E1S_0_RX_DP2: length 36.7
  TOP w0.132: v3(30.03,29.76) 30.37,30.1 30.81,30.1 31.51,30.8 31.86,30.8 31.97,30.69 J4.A24
  BOTTOM w0.132: GF1.A24 33.65,3.16 33.52,3.29 33.52,4.63 33.75,5.6 34.03,6.82 35.74,9.27 35.86,10.82 v4(35.92,11.64) 35.98,12.37 36.16,14.74 35.21,15.89 35.21,15.89 31.4,20.53 31.42,20.82 31.17,21.13 30.88,21.16 30.63,21.46 30.66,21.75 30.41,22.05 30.12,22.08 29.87,22.39 29.9,22.67 29.65,22.98 29.36,23.01 28.74,23.76 28.74,23.76 28.13,24.51 28.13,28.26 28.28,29.16 28.56,29.55 29.11,30.1 29.77,30.1 30.03,29.84 v3(30.03,29.76)
P3E_E1S_0_RX_DP3: length 35.8
  TOP w0.132: J4.A27 33.6,28.89 33.73,29.02 34.28,29.02 v3(34.62,28.69)
  BOTTOM w0.132: v3(34.62,28.69) 34.62,28.8 34.41,29.02 33.54,29.02 33.11,28.58 33.11,27.88 33.27,27.64 33.5,27.31 33.79,27.26 34.01,26.94 33.96,26.66 34.19,26.33 34.48,26.28 34.7,25.96 34.65,25.67 35.53,24.43 35.55,24.4 35.65,24.26 35.66,24.26 35.76,24.1 35.94,23.83 36.16,23.52 36.26,22.82 36.49,22.65 36.55,22.26 36.37,22.03 36.46,21.46 36.61,21.35 36.76,21.37 37.2,21.44 37.57,21.15 37.69,20.38 37.41,20 36.81,19.92 36.7,19.77 36.78,19.27 36.92,19.16 37.52,19.24 37.89,18.96 38,18.18 37.72,17.81 37.13,17.72 37.02,17.57 37.42,14.84 v4(37.48,14.42) 37.51,14.19 37.53,14.09 37.33,11.92 37.01,8.33 35.74,7.06 35.32,6.12 35.32,3.29 35.45,3.16 GF1.A27
P3E_E1S_0_TX_DN0: length 40.5
  TOP w0.132: GF1.B17 29.45,3.16 29.58,3.29 29.58,6.33 31.58,9.18 32.04,11.8 32,14.22 31.85,15 23.32,23.37 22.93,25.63 v4(22.93,31) 22.93,31.91 23,32.33 24.55,33.42 26.29,34.63 26.81,34.8 27.26,34.8 27.35,34.89 J4.B17
P3E_E1S_0_TX_DN1: length 39.5
  TOP w0.132: GF1.B20 31.25,3.16 31.38,3.29 31.38,6.62 33.44,9.56 v4(33.44,10.71) 33.44,11.68 33.77,12.01 34.33,12.01 34.46,12.14 34.46,12.64 34.33,12.77 33.77,12.77 33.44,13.1 33.44,14.59 33.43,14.69 33.02,15.66 24.57,23.96 24.36,25.16 24.36,30.99 24.47,31.61 25.66,32.45 26.28,32.86 26.41,32.92 26.73,32.99 27.32,32.99 27.42,33.09 J4.B20
P3E_E1S_0_TX_DN2: length 35.7
  TOP w0.132: GF1.B23 33.05,3.16 33.18,3.29 33.18,6.29 35.69,9.87 v4(35.69,12.57) 35.69,13.06 35.61,13.89 35.16,15.01 34.6,15.85 25.93,24.48 25.79,24.81 25.79,30.01 25.95,30.37 26.16,30.82 26.69,31.19 27.38,31.19 27.48,31.29 J4.B23
P3E_E1S_0_TX_DN3: length 34.8
  TOP w0.132: GF1.B26 34.85,3.16 34.97,3.27 34.97,6.68 37.08,9.7 v4(37.08,14.86) 37.08,15.13 36.62,15.61 36.62,16.08 37.17,16.61 37.17,16.7 36.77,17.11 36.58,17.11 36.09,16.63 35.62,16.64 33.7,18.61 32.09,20.26 28.21,24.25 27.35,25.79 27.35,26.63 27.1,27.43 26.88,28.16 26.85,28.44 26.82,28.76 26.99,29.19 27.23,29.39 27.44,29.39 27.55,29.49 J4.B26
P3E_E1S_0_TX_DP0: length 40.5
  TOP w0.132: GF1.B18 30.05,3.16 29.92,3.29 29.92,6.23 31.9,9.05 32.38,11.78 32.34,14.26 32.16,15.17 23.64,23.54 23.27,25.66 v4(23.27,27.09) 23.27,28.29 23.47,28.49 23.47,28.88 23.27,29.09 23.27,29.48 23.47,29.69 23.47,30.08 23.27,30.29 23.27,30.68 23.47,30.89 23.47,31.28 23.27,31.49 23.27,31.88 23.31,32.13 24.75,33.14 26.23,34.18 26.29,34.22 26.44,34.32 26.87,34.46 27.26,34.46 27.42,34.29 J4.B18
P3E_E1S_0_TX_DP1: length 39.5
  TOP w0.132: GF1.B21 31.85,3.16 31.72,3.29 31.72,6.52 33.78,9.46 33.78,11.53 33.91,11.67 34.47,11.67 34.8,12 34.8,12.78 34.47,13.11 33.91,13.11 33.78,13.25 v4(33.78,14.35) 33.78,14.61 33.76,14.77 33.31,15.85 24.89,24.13 24.7,25.19 24.7,27.36 24.9,27.57 24.9,27.96 24.7,28.17 24.7,28.56 24.9,28.77 24.9,29.16 24.7,29.37 24.7,29.76 24.9,29.97 24.9,30.36 24.7,30.57 24.7,30.96 24.78,31.41 25.85,32.17 26.29,32.46 26.45,32.57 26.52,32.6 26.77,32.65 27.26,32.65 27.42,32.49 J4.B21
P3E_E1S_0_TX_DP2: length 35.7
  TOP w0.132: GF1.B24 33.65,3.16 33.52,3.29 33.52,6.19 36.03,9.76 36.03,13.08 35.94,13.97 35.46,15.17 34.86,16.07 v4(29.34,21.56) 28.55,22.35 27.96,22.94 27.96,23.23 27.68,23.51 27.39,23.51 26.22,24.67 26.13,24.87 26.13,25.07 26.34,25.27 26.34,25.67 26.13,25.87 26.13,26.27 26.34,26.47 26.34,26.87 26.13,27.07 26.13,29.94 26.27,30.25 26.29,30.29 26.43,30.59 26.8,30.85 27.26,30.85 27.42,30.69 J4.B24
P3E_E1S_0_TX_DP3: length 34.8
  TOP w0.132: GF1.B27 35.45,3.16 35.31,3.31 35.31,6.57 37.42,9.59 v4(37.42,10.67) 37.42,15.27 36.96,15.75 36.96,15.94 37.51,16.47 37.51,16.84 36.91,17.45 36.45,17.46 35.95,16.97 35.76,16.98 33.94,18.85 32.33,20.5 32.34,20.79 32.06,21.08 31.77,21.08 31.5,21.36 31.5,21.65 31.23,21.93 30.94,21.94 30.66,22.22 30.67,22.51 30.39,22.79 30.1,22.8 28.49,24.45 27.69,25.88 27.69,26.69 27.21,28.23 27.17,28.71 27.28,28.98 27.36,29.05 27.52,29.05 27.67,28.89 J4.B27
P3E_E1S_1_RX_DN0: length 46.7
  TOP w0.132: J5.A17 57.52,34.9 57.39,34.77 56.37,34.77 v3(56.03,35.1)
  BOTTOM w0.132: GF1.A30 40.66,3.16 40.8,3.3 40.8,4.17 41.04,5.6 41.05,5.66 41.05,5.66 41.34,7.4 42.82,10.98 50.96,15.88 52.11,17.03 52.4,18.66 52.11,21.1 49.93,24.21 49.29,27.84 49.29,31.67 50.44,33.31 v4(50.63,33.58) 50.93,34.01 50.93,34.01 51.31,34.55 51.72,34.63 54,35.03 55.46,34.77 55.7,34.77 v3(56.03,35.1)
P3E_E1S_1_RX_DN1: length 46.7
  TOP w0.132: v3(60.17,33.3) 59.83,32.97 59.23,32.97 59.1,33.09 J5.A20
  BOTTOM w0.132: GF1.A33 42.46,3.16 42.59,3.29 42.59,5.94 42.63,6.65 43.86,10.17 50.27,14.03 51.51,14.64 51.51,14.64 52.44,15.29 52.96,16.04 53.58,16.92 53.82,17.25 54.04,18.54 54.05,19.21 53.66,21.32 53.42,21.9 51.61,24.48 51.36,25.91 51.26,26.46 51.26,26.46 50.83,28.88 51.01,29.87 51.01,29.87 51.1,30.37 51.59,30.71 v4(51.86,30.91) 52.19,31.14 52.7,31.14 54.79,32.6 56.29,32.6 56.75,32.92 56.86,32.94 57.52,32.94 58.56,33.12 59.44,32.97 59.83,32.97 v3(60.17,33.3)
P3E_E1S_1_RX_DN2: length 39.4
  TOP w0.132: v3(55.53,30.78) 55.53,30.73 55.85,30.4 56.18,30.4 56.95,31.17 57.39,31.17 57.52,31.3 J5.A23
  BOTTOM w0.132: GF1.A36 44.26,3.16 44.39,3.29 44.39,6.1 44.42,6.78 45.2,9.54 45.23,9.56 45.7,9.85 48.28,11.4 50.71,12.86 50.86,12.95 52.14,13.58 53.25,14.36 53.61,14.7 54.13,15.18 55.18,16.68 55.34,17.59 v4(55.42,18.02) 55.5,18.5 55.57,18.9 55.03,22.04 53.03,24.9 53.03,26.08 53.22,27.17 53.24,27.29 53.24,27.32 53.66,29.67 54.76,30.44 55.28,30.44 55.53,30.69 v3(55.53,30.78)
P3E_E1S_1_RX_DN3: length 38.7
  TOP w0.132: v3(60.12,29.7) 59.78,29.37 59.06,29.37 58.93,29.49 J5.A26
  BOTTOM w0.132: GF1.A39 46.06,3.16 46.19,3.29 46.19,7.66 46.75,8.95 52.38,12.33 53.43,12.85 55.5,14.79 56.69,16.3 v4(57.03,16.75) 57.77,17.69 58.82,19.04 59.15,20.64 59.54,20.9 59.8,20.85 59.95,20.95 60.05,21.45 59.95,21.6 59.69,21.65 59.43,22.04 59.91,24.41 59.82,24.83 58.79,26.31 58.79,26.31 58.06,27.35 57.96,27.89 58.11,28.75 58.73,29.37 59.78,29.37 v3(60.12,29.7)
P3E_E1S_1_RX_DP0: length 46.7
  TOP w0.132: v3(56.03,34.09) 56.37,34.42 57.39,34.42 57.52,34.3 J5.A18
  BOTTOM w0.132: v3(56.03,34.09) 56.03,34.13 55.74,34.43 55.43,34.43 54,34.68 52.01,34.33 51.87,34.31 51.51,34.24 51.29,33.93 51.34,33.64 51.11,33.32 50.82,33.27 50.6,32.94 50.37,32.62 50.42,32.34 50.2,32.01 49.91,31.96 49.63,31.56 49.63,31.13 49.84,30.93 49.84,30.53 49.63,30.33 v4(49.63,28.67) 49.63,27.87 50.25,24.35 52.44,21.22 52.74,18.65 52.43,16.87 51.17,15.61 43.09,10.74 41.67,7.3 41.38,5.6 41.14,4.14 41.14,3.28 41.26,3.16 GF1.A31
P3E_E1S_1_RX_DP1: length 46.7
  TOP w0.132: v3(60.17,32.29) 59.83,32.62 59.23,32.62 59.1,32.49 J5.A21
  BOTTOM w0.132: GF1.A34 43.06,3.16 42.93,3.29 42.93,5.93 42.97,6.59 44.14,9.94 47.29,11.84 50.43,13.73 51.68,14.34 51.7,14.36 52.69,15.05 53.19,15.76 53.86,16.73 54.14,17.12 54.18,17.37 54.18,17.37 54.22,17.58 v4(54.28,17.9) 54.34,18.27 54.38,18.51 54.39,19.24 53.99,21.42 53.72,22.06 51.93,24.61 51.75,25.63 51.6,26.52 51.6,26.52 51.76,26.76 51.69,27.15 51.46,27.31 51.39,27.7 51.55,27.94 51.49,28.33 51.25,28.49 51.18,28.88 51.35,29.83 51.35,29.83 51.41,30.17 52.3,30.8 52.81,30.8 53.91,31.57 54.2,31.52 54.52,31.75 54.57,32.03 54.89,32.26 56.4,32.26 56.89,32.59 56.89,32.6 57.55,32.6 58.56,32.77 59.41,32.62 59.88,32.62 60.17,32.34 v3(60.17,32.29)
P3E_E1S_1_RX_DP2: length 39.4
  TOP w0.132: v3(55.53,29.76) 55.83,30.06 56.33,30.06 57.09,30.82 57.39,30.82 57.52,30.7 J5.A24
  BOTTOM w0.132: v3(55.53,29.76) 55.19,30.1 54.86,30.1 53.97,29.47 53.9,29.08 54.07,28.85 54,28.46 53.76,28.29 53.69,27.9 53.86,27.67 53.79,27.28 53.56,27.11 53.37,26.05 53.37,25.01 54.58,23.28 54.87,23.23 55.09,22.91 55.04,22.62 55.36,22.17 55.45,21.61 55.69,21.44 55.76,21.05 55.59,20.82 55.68,20.28 55.73,20 55.78,19.69 55.92,18.89 55.5,16.55 54.39,14.96 53.48,14.11 53.46,14.09 52.31,13.29 51.02,12.66 50.73,12.48 48.39,11.07 46.48,9.92 45.49,9.33 44.76,6.73 44.73,6.09 44.73,3.29 44.86,3.16 GF1.A37
P3E_E1S_1_RX_DP3: length 38.7
  TOP w0.132: J5.A27 59.1,28.9 59.23,29.02 59.78,29.02 v3(60.12,28.69)
  BOTTOM w0.132: v3(60.12,28.69) 60.12,28.75 59.85,29.02 58.87,29.02 58.43,28.59 58.31,27.89 58.38,27.48 58.61,27.16 58.89,27.11 59.12,26.79 59.07,26.5 59.29,26.18 59.58,26.13 59.81,25.8 59.76,25.52 60.14,24.97 60.25,24.41 59.79,22.12 59.89,21.96 60.16,21.91 60.42,21.52 60.26,20.75 59.87,20.49 59.61,20.54 59.45,20.44 59.36,19.98 v4(59.28,19.58) 59.21,19.23 59.14,18.9 55.75,14.56 53.63,12.57 52.54,12.04 51.36,11.32 51.29,11.04 50.95,10.84 50.67,10.91 47.02,8.71 46.53,7.59 46.53,3.29 46.66,3.16 GF1.A40
P3E_E1S_1_TX_DN0: length 42.1
  TOP w0.132: J5.B17 52.9,34.9 52.81,34.8 52.01,34.8 49.44,33 48.72,32.27 v4(47.53,30.58) 47,29.83 46.8,28.69 46.8,27.97 46.94,27.17 47.17,25.88 47.29,25.7 47.3,25.7 47.66,25.17 47.67,25.16 50.93,20.51 50.93,17.94 49.76,16.28 44.44,12.55 44.31,12.37 44,12.06 41.21,8.08 40.79,5.7 40.79,3.29 40.66,3.16 GF1.B30
P3E_E1S_1_TX_DN1: length 40.9
  TOP w0.132: J5.B20 52.91,33.09 52.78,32.97 52.24,32.97 51.82,32.77 51.28,32.51 50.56,32.01 v4(50.44,31.92) 50.09,31.67 49.45,31.04 49.4,30.98 48.18,29.23 48.29,28.6 48.29,28.59 48.8,25.72 53.51,18.99 53.51,17.69 53.41,17.27 46.55,12.46 44,9.92 42.59,7.9 42.59,3.28 42.46,3.16 GF1.B33
P3E_E1S_1_TX_DN2: length 38.1
  TOP w0.132: J5.B23 52.92,31.3 52.84,31.22 51.98,31.22 51.82,31.11 50.85,30.43 49.8,28.92 v4(49.89,28.38) 49.97,27.94 50.38,25.63 53.68,20.91 54.73,19.41 54.73,16.7 53.27,15.67 47.34,11.52 46.11,10.29 44.39,7.84 44.39,3.29 44.26,3.16 GF1.B36
P3E_E1S_1_TX_DN3: length 37.3
  TOP w0.132: GF1.B39 46.06,3.16 46.19,3.29 46.19,7.5 46.4,8.42 48.8,10.82 51.93,13.01 v4(52.44,13.37) 54.77,15 54.9,15.09 55.73,15.67 56.07,15.91 56.07,17.96 56.4,18.29 57.16,18.29 57.29,18.42 57.29,18.92 57.16,19.06 56.4,19.06 56.07,19.39 56.07,20.01 51.95,25.89 51.77,26.15 51.46,27.89 51.46,28.71 52.01,29.25 52.03,29.27 52.2,29.39 52.81,29.39 52.92,29.49 J5.B26
P3E_E1S_1_TX_DP0: length 42.1
  TOP w0.132: J5.B18 52.92,34.3 52.76,34.46 52.12,34.46 51.79,34.23 51.74,33.94 51.42,33.72 51.13,33.77 50.81,33.54 50.76,33.25 50.43,33.03 50.14,33.08 49.66,32.74 48.98,32.05 47.32,29.69 47.14,28.66 47.14,28 v4(47.21,27.59) 47.28,27.23 47.52,27.06 47.58,26.67 47.42,26.43 47.49,26.01 47.58,25.89 47.94,25.36 51.27,20.62 51.27,17.83 50.01,16.03 44.68,12.3 44.57,12.15 44.26,11.84 41.53,7.94 41.13,5.67 41.13,3.29 41.26,3.16 GF1.B31
P3E_E1S_1_TX_DP1: length 40.9
  TOP w0.132: J5.B21 52.92,32.49 52.78,32.63 52.32,32.63 51.82,32.39 51.46,32.22 50.76,31.73 50.76,31.73 50.64,31.65 50.64,31.64 50.31,31.41 49.7,30.81 49.68,30.77 49.57,30.62 49.62,30.33 49.39,30.01 49.11,29.96 48.72,29.41 48.54,29.15 48.62,28.66 48.63,28.65 48.66,28.47 48.9,28.3 48.96,27.91 48.8,27.68 48.87,27.29 49.1,27.12 49.17,26.73 49.01,26.5 49.01,26.47 49.12,25.85 53.85,19.1 53.85,17.65 53.71,17.07 46.77,12.2 v4(45.98,11.42) 44.26,9.7 42.93,7.79 42.93,3.3 43.06,3.16 GF1.B34
P3E_E1S_1_TX_DP2: length 38.2
  TOP w0.132: J5.B24 52.92,30.7 52.74,30.88 52.08,30.88 51.1,30.19 50.95,29.97 51,29.69 50.77,29.36 50.49,29.31 50.16,28.84 50.22,28.46 50.46,28.29 50.53,27.9 50.36,27.66 50.43,27.27 50.67,27.1 50.74,26.72 50.57,26.48 50.7,25.77 53.64,21.56 v4(53.87,21.23) 54.22,20.73 55.07,19.52 55.07,16.52 53.46,15.39 47.56,11.26 46.37,10.07 44.73,7.74 44.73,3.29 44.86,3.16 GF1.B37
P3E_E1S_1_TX_DP3: length 37.3
  TOP w0.132: J5.B27 52.97,28.9 52.82,29.05 52.3,29.05 52.24,29 52.24,29 51.81,28.57 51.81,27.92 52.09,26.28 52.23,26.08 52.52,26.03 52.75,25.71 52.7,25.42 52.92,25.1 53.21,25.05 53.43,24.73 53.38,24.44 53.66,24.05 54.3,23.13 54.59,23.08 54.81,22.76 54.76,22.47 56.41,20.11 56.41,19.53 56.55,19.4 57.3,19.4 57.63,19.06 57.63,18.28 57.3,17.95 56.55,17.95 56.41,17.82 56.41,15.74 56.38,15.71 54.98,14.73 v4(54.96,14.72) 49.03,10.56 46.71,8.25 46.53,7.46 46.53,3.29 46.66,3.16 GF1.B40
P3E_E1S_2_RX_DN0: length 50.1
  TOP w0.132: J6.A17 83.02,34.9 82.89,34.77 81.87,34.77 v3(81.54,35.1)
  BOTTOM w0.132: v3(81.54,35.1) 81.2,34.77 80.61,34.77 80.12,34.42 79.67,34.11 79.24,33.49 78.51,32.98 77.74,32.98 75.23,31.22 71.88,26.43 71.29,23.13 71.21,22.68 71.15,22.31 70.6,19.22 70.34,19.03 65.6,18.2 64.43,17.99 61.47,15.92 v4(61.14,15.69) 60.6,15.31 59.29,14.39 53.5,6.13 53.5,3.29 53.37,3.16 GF1.A44
P3E_E1S_2_RX_DN1: length 51.1
  TOP w0.132: v3(85.67,33.3) 85.33,32.97 84.73,32.97 84.6,33.09 J6.A20
  BOTTOM w0.132: GF1.A47 55.17,3.16 55.3,3.29 55.3,6.05 60.57,13.57 64.99,16.67 71.08,17.74 72.14,18.48 73.48,26.05 v4(74.5,27.5) 74.52,27.53 74.71,27.82 76.45,30.29 76.48,30.34 76.53,30.38 77.62,31.14 78.53,31.14 80.53,32.54 81.01,32.62 81.74,32.62 82.28,32.87 83.44,33.11 84.27,32.95 85.31,32.95 v3(85.67,33.3)
